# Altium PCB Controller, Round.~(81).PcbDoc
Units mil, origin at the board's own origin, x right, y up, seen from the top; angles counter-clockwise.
Board outline 1800 x 1800 mil, 4 copper layers (Top Layer, MidLayer1, MidLayer2, Bottom Layer); 43 components, 69 nets, 207 pads, 107 vias.
Unrouted connection lines stored in the file: 18.
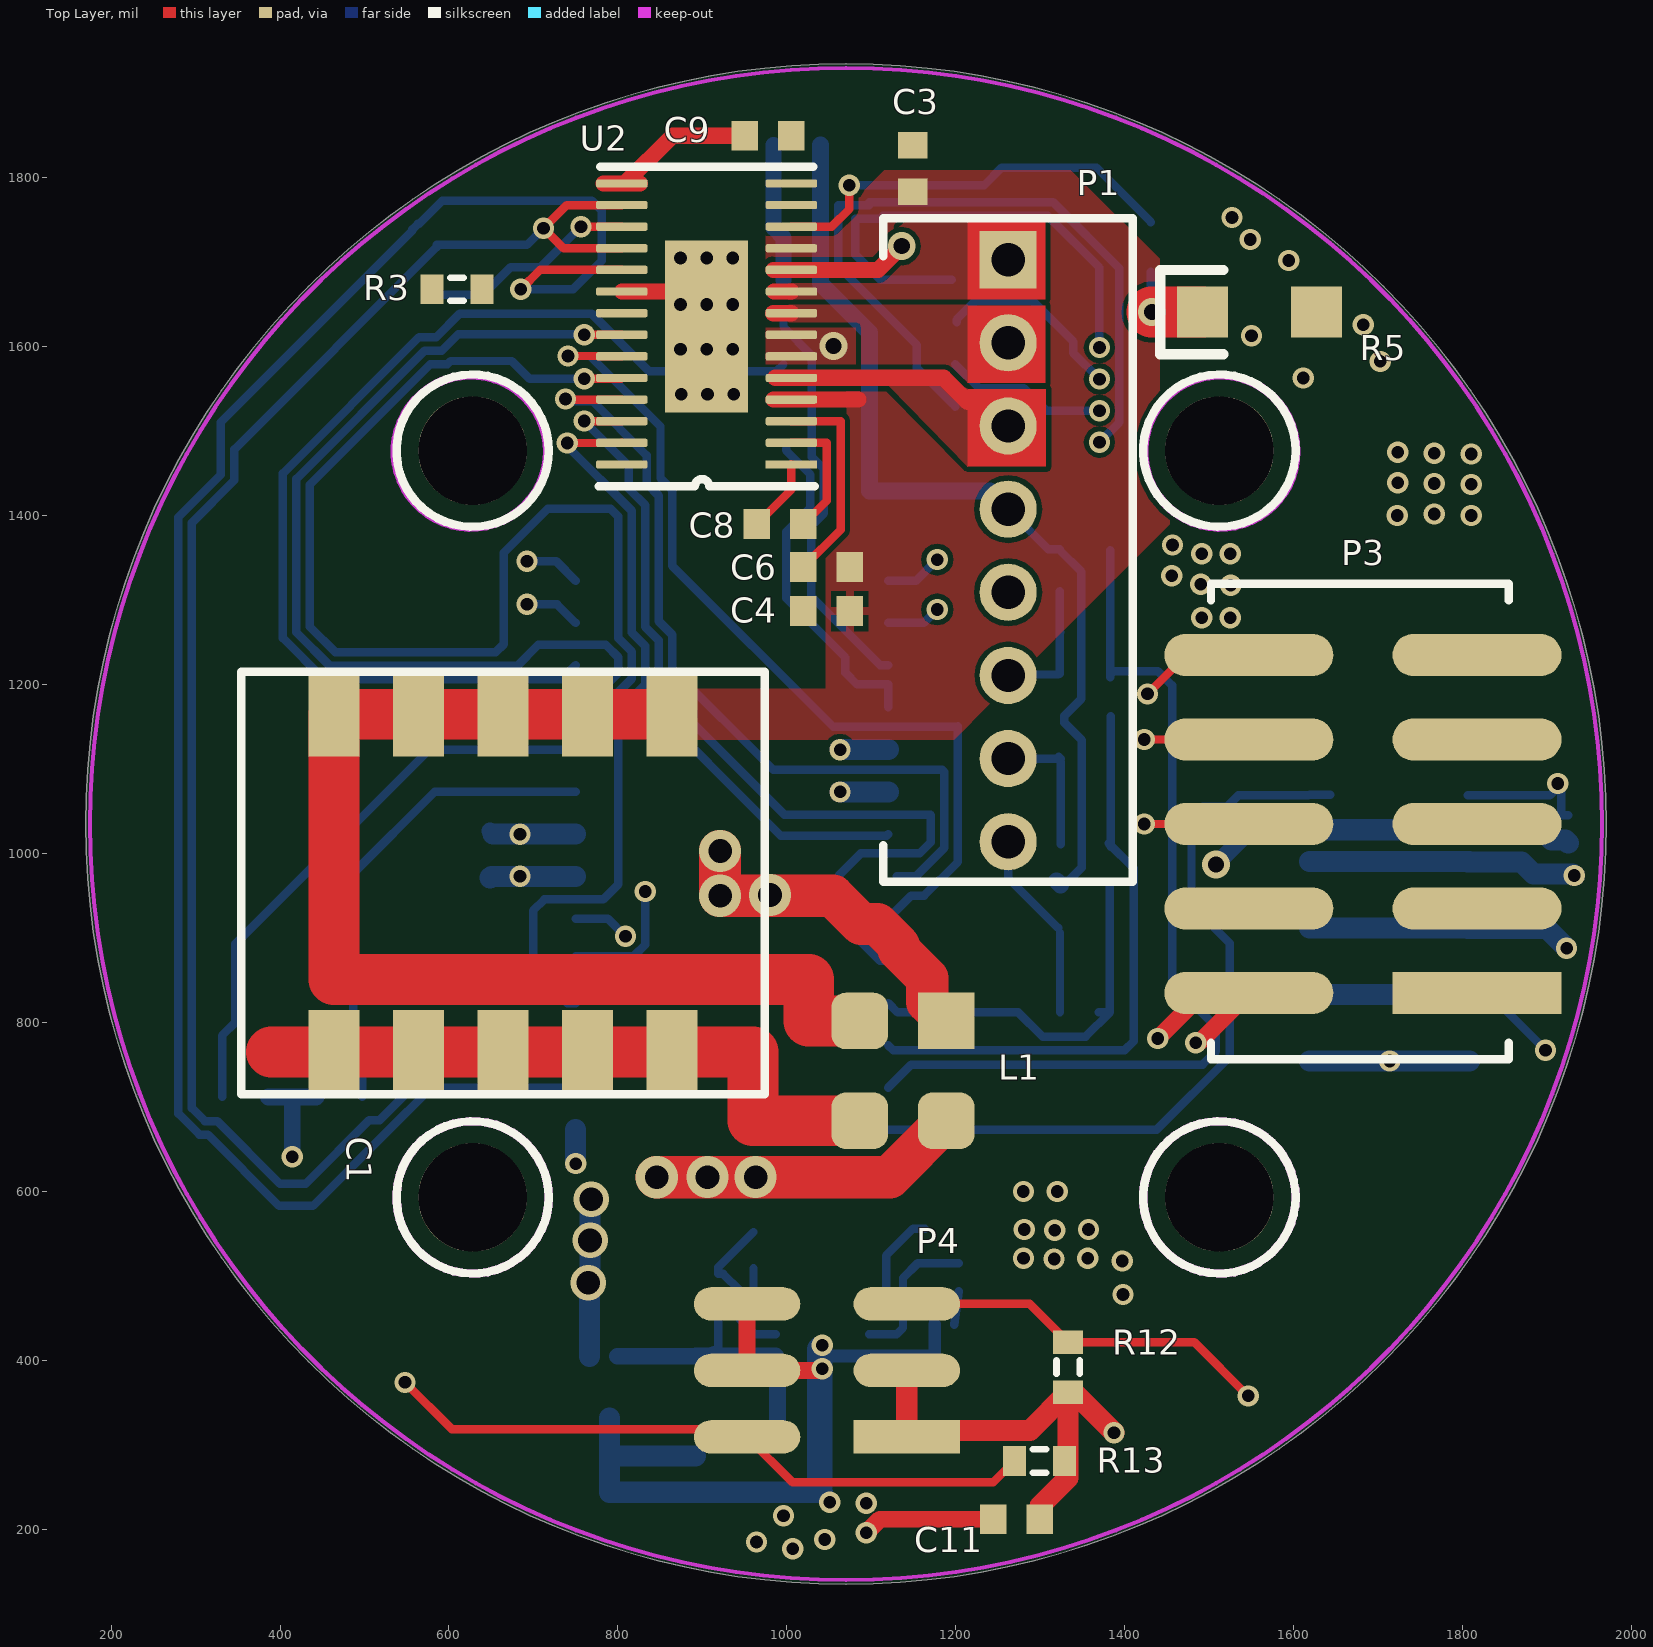
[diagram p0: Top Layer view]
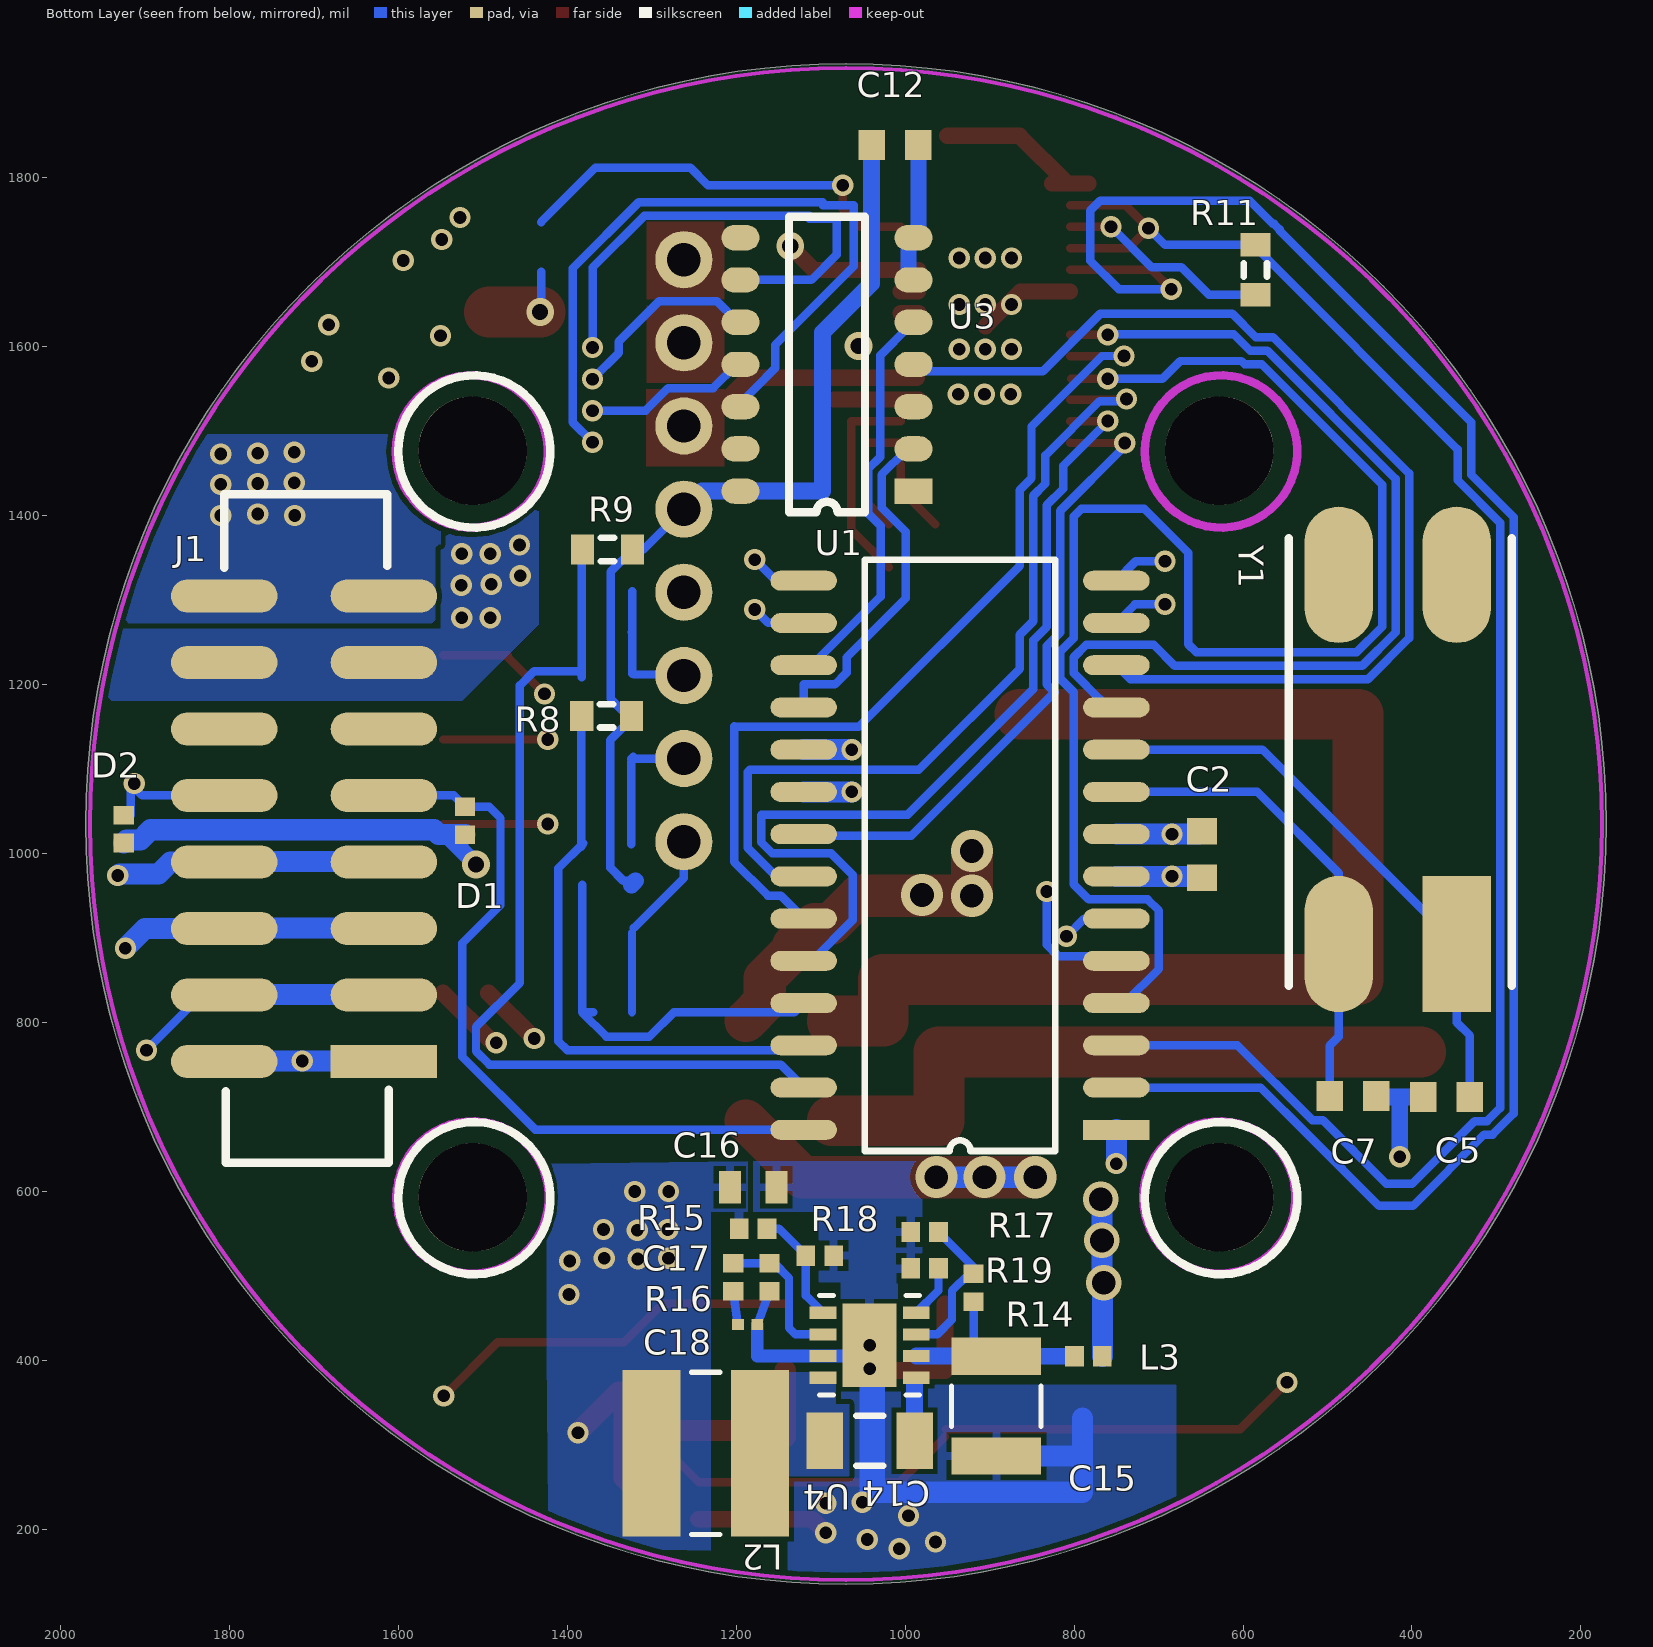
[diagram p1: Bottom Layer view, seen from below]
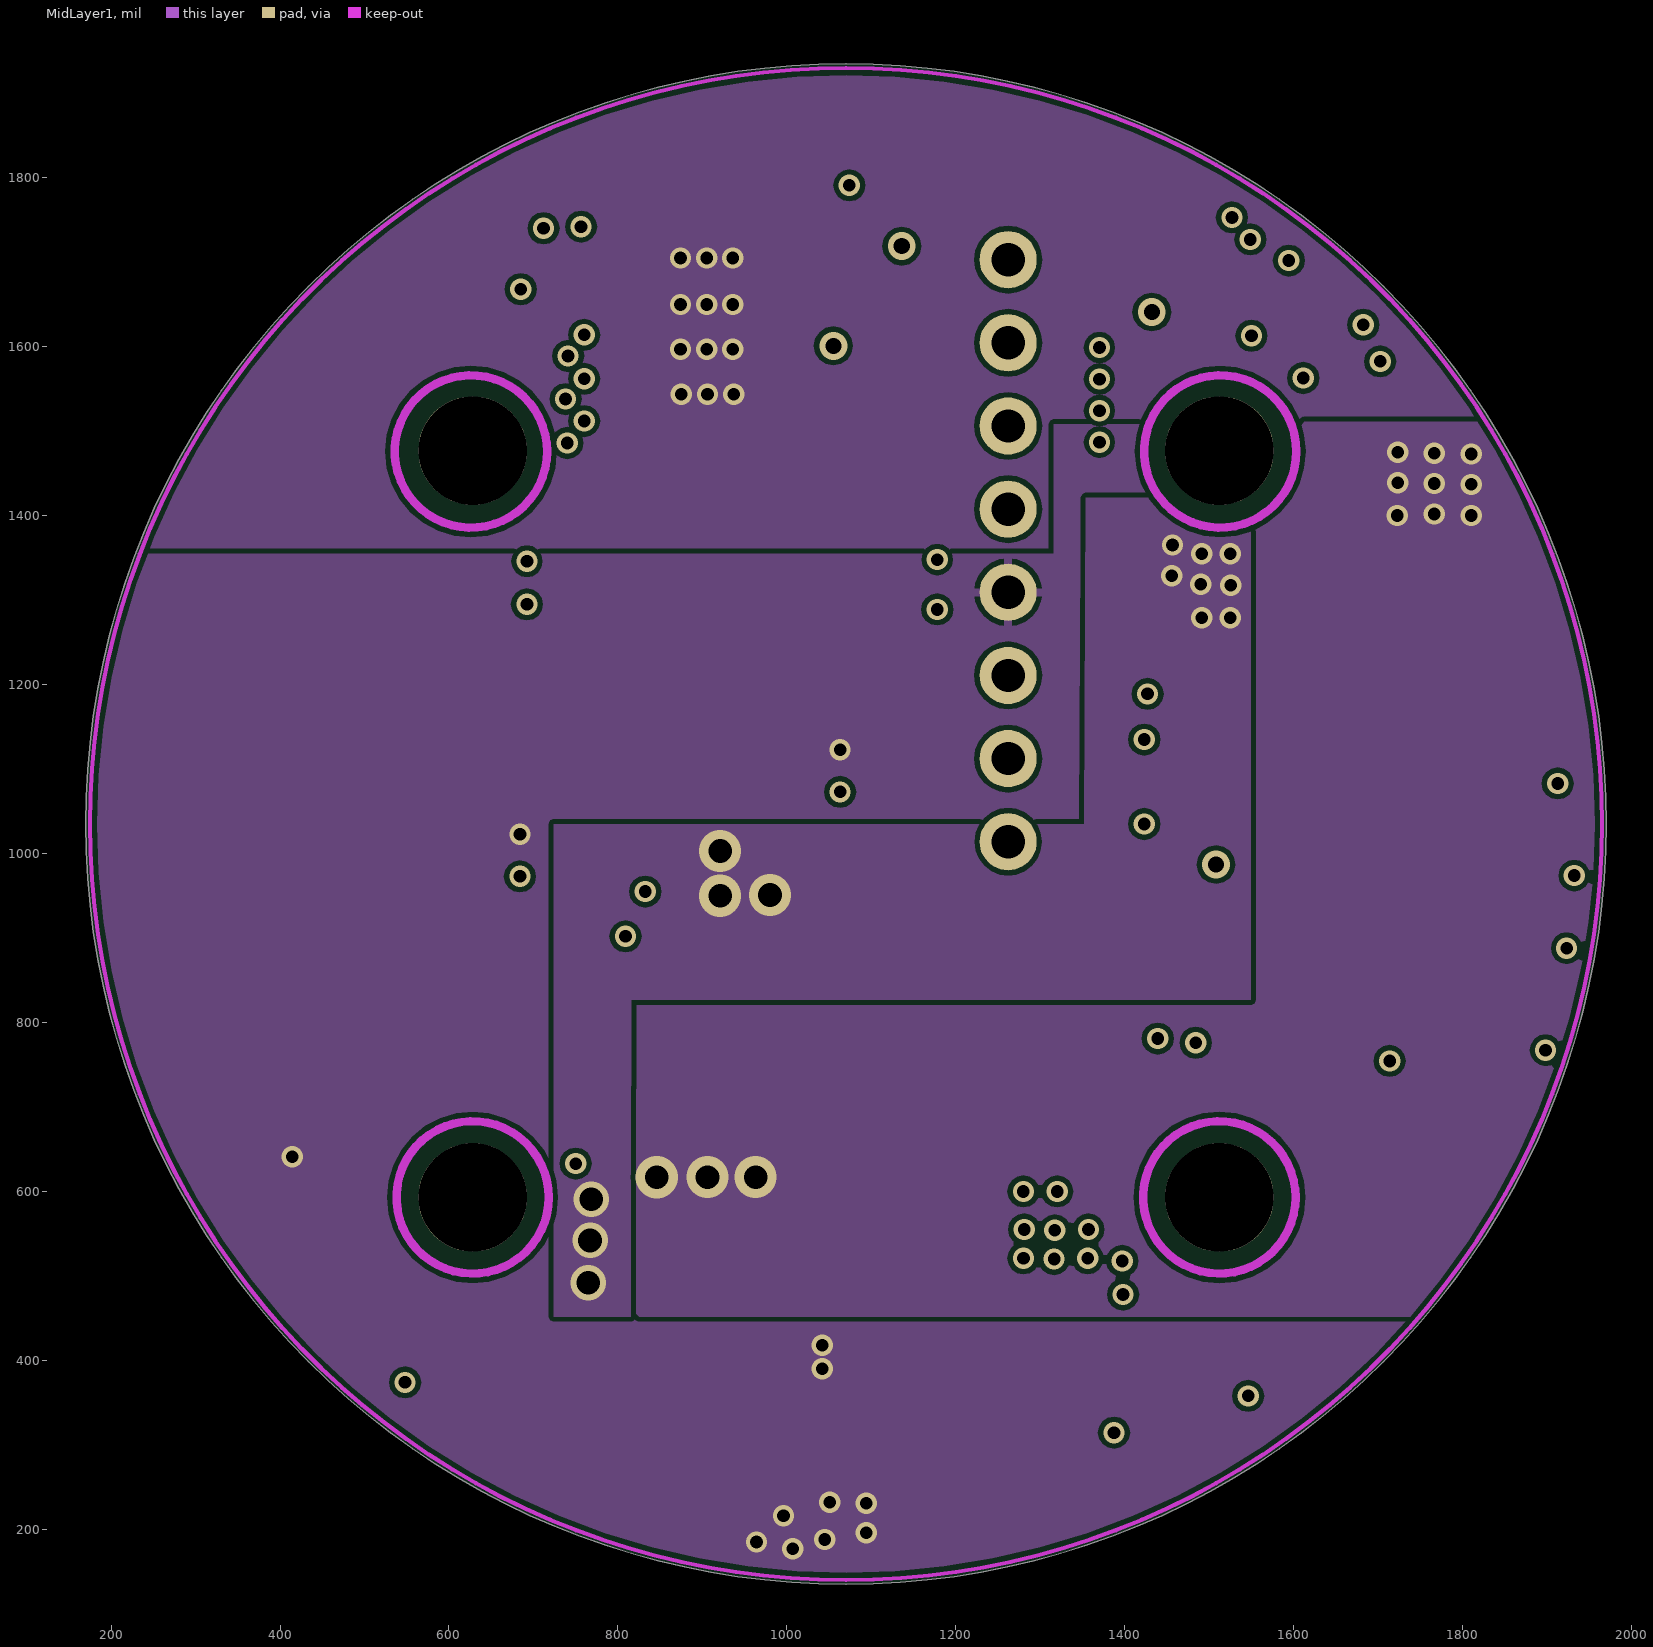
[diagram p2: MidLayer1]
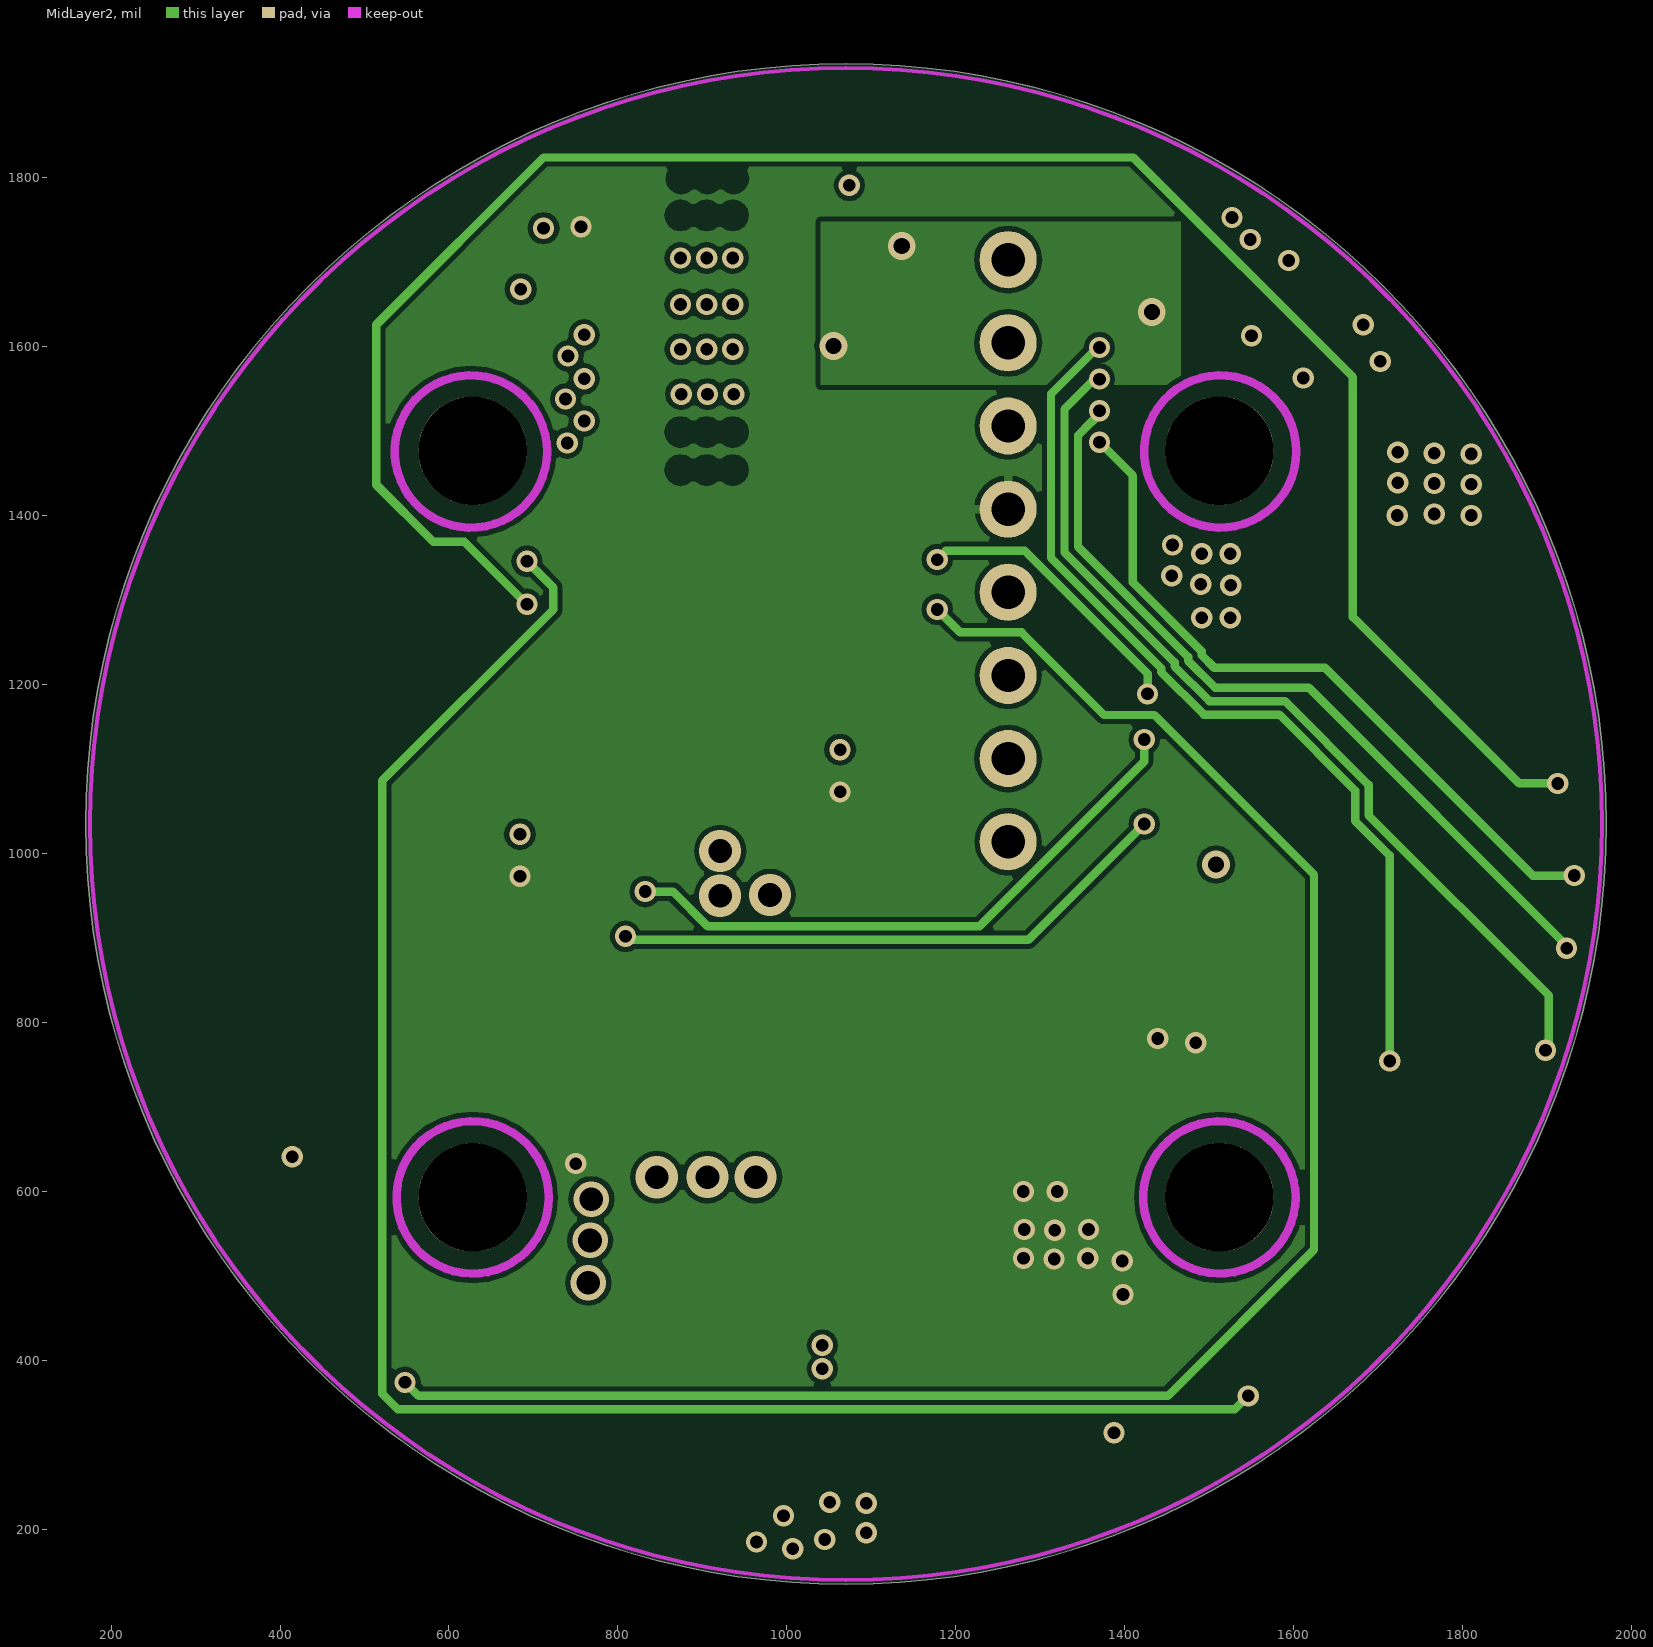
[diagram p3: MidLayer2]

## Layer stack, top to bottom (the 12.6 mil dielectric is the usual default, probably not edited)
Top Solder: solder mask 0.4, Solder Resist, Dk 3.5
Top Layer: signal copper 1.4
Dielectric1: core 12.6, FR-4, Dk 4.8
MidLayer1: signal copper 1.4
Dielectric2: prepreg 12.6, FR-4, Dk 4.8
MidLayer2: signal copper 1.4
Dielectric3: core 12.6, FR-4, Dk 4.8
Bottom Layer: signal copper 1.4
Bottom Solder: solder mask 0.4, Solder Resist, Dk 3.5

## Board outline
1070,135 cw(c1070,1035) 170,1035 cw(c1070,1035) 1070,1935 cw(c1070,1035) 1970,1035 cw(c1070,1035)

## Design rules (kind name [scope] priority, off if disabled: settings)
Clearance [All] p1: gap=6 ignorepadtopadclearanceinfootprint=FALSE except(0: Arc-Hole Track-Hole SMDPad-Hole THPad-Hole Via-Hole Fill-Hole Poly-Hole Region-Hole Text-Hole)
HoleSize [All] p1: absolutevalues=TRUE maxlimit=130 minlimit=15 maxpercent=80.000 minpercent=20.000
MinimumAnnularRing AdvancedCircuitsAnnularRing [All] p1: minimumring=5.1
MinimumSolderMaskSliver [All] p1: minsoldermaskwidth=5
PolygonConnect PolygonConnect_Via [IsVia] p1: connectstyle=Direct reliefconductorwidth=10 reliefentries=4 polygonreliefangle="90 Angle" airgapwidth=10
PolygonConnect PolygonConnect_7 [InComponent('U2') vs InNet('GND')] p2: connectstyle=Relief reliefconductorwidth=10 reliefentries=4 polygonreliefangle="90 Angle" airgapwidth=10
PolygonConnect PolygonConnect_6 [InComponent('L1') vs InNet('GND')] p3: connectstyle=NoConnect reliefconductorwidth=10 reliefentries=4 polygonreliefangle="90 Angle" airgapwidth=10
PolygonConnect PolygonConnect_5 [InComponent('L2') vs InNet('VCC')] p4: connectstyle=Direct reliefconductorwidth=10 reliefentries=4 polygonreliefangle="90 Angle" airgapwidth=10
PolygonConnect PolygonConnect_4 [(InComponent('R19') OR InComponent('R17') OR InComponent('U4')) vs InNet('SGND')] p5: connectstyle=Direct reliefconductorwidth=10 reliefentries=4 polygonreliefangle="90 Angle" airgapwidth=10
PolygonConnect PolygonConnect_3 [All vs InNet('NetC14_1')  or InNet('NetJ1_13')  or InNet('NetJ1_15')] p6: connectstyle=Direct reliefconductorwidth=10 reliefentries=4 polygonreliefangle="90 Angle" airgapwidth=10
PolygonConnect PolygonConnect_2 [InComponent('C4')] p7: connectstyle=Relief reliefconductorwidth=10 reliefentries=4 polygonreliefangle="90 Angle" airgapwidth=10
PolygonConnect PolygonConnect_1 [(InComponent('C1')) vs InNet('GND')] p8: connectstyle=NoConnect reliefconductorwidth=10 reliefentries=4 polygonreliefangle="90 Angle" airgapwidth=10
PolygonConnect [(InNet('NetP1_1') OR InNet('NetP1_2') OR InNet('NetP1_3') OR InNet('VM') OR InNet('VSENSE')) vs (InNet('NetP1_1') OR InNet('NetP1_2') OR InNet('NetP1_3') OR InNet('VM') OR InNet('VSENSE'))] p9: connectstyle=Direct reliefconductorwidth=10 reliefentries=4 polygonreliefangle="90 Angle" airgapwidth=10
RoutingVias RoutingVias_1 [(InNet('ADDR_IN') OR InNet('ADDR_OUT'))] p1: holewidth=15 width=25 viastyle="Through Hole" minholewidth=15 minwidth=25 maxholewidth=15 maxwidth=25
RoutingVias [All] p2: holewidth=15 width=25 viastyle="Through Hole" minholewidth=15 minwidth=25 maxholewidth=28 maxwidth=50
SilkToSolderMaskClearance SilkscreenOverComponentPads [IsPad] p1: minsilkscreentomaskgap=10 clearancetoexposedcopper=TRUE
SolderMaskExpansion [All] p1: expansion=4
Width Width_2 [All] p1: maxlimit=100 minlimit=6 preferedwidth=10 checkconnectedcopper=TRUE
Width Width_3 [InNet('VM')] p2: maxlimit=100 minlimit=20 preferedwidth=40
27 further rules are at their usual default settings.

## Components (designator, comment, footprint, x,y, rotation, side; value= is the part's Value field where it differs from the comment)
C1 "Cap" CAPSTICK-CS4-5-SMD 464,1165 r0 top value=10uf
C2 "Cap Semi" 1608[0603] 648.62,999 r90 bottom value=15pf
C3 "Cap Semi" 1608[0603] 1149,1811 r270 top value=.1uf
C4 "Cap Semi" 1608[0603] 1047,1287 r0 top value=.1uf
C5 "Cap Semi" 1608[0603] 359,712 r180 bottom value=15pf
C6 "Cap Semi" 1608[0603] 1047,1339 r0 top value=.1uf
C7 "Cap Semi" 1608[0603] 470,713 r0 bottom value=15pf
C8 "Cap Semi" 1608[0603] 992,1390 r180 top value=.01uf
C9 "Cap Semi" 1608[0603] 977.61,1849.7 r180 top value=.47uF
C11 "Cap Semi" 1608[0603] 1272,212 r0 top value=15pf
C12 "Cap Semi" 1608[0603] 1012,1839 r180 bottom value=15pf
C14 "C1005X7R1E103K" C1206 1042,305 r180 bottom value=10nF
C15 "C3225X7R2A225K230AB" 1210 892,346 r270 bottom value=2.2uF
C16 "C1608X5R0J106M" 0603 1180,605 r180 bottom value=10uF
C17 "C0402C330J5GAC" 0402 1160.5,498.5 r270 bottom value=33pF
C18 "GRM033R61A472KA01D" 0201 1186.5,442.5 r180 bottom value=4.7nF
D1 "Tranzorb" 0402 1521,1039 r90 bottom
D2 "Tranzorb" 0402 1925,1029 r90 bottom
J1 "M80-8281642" M80-828XXXXDIL 1806,1305 r180 bottom
L1 "DLW5BTN501SQ2" DLW5A_5B 1086.3,801.85 r0 top locked
L2 "LPS5030-823MLB" LPS5030 1236,290 r180 bottom value=82uH
L3 "INDUCTOR" 0402 783,405 r0 bottom
P1 "MKS 1658-6-0-808" MKS_1658_A_KF 1261.92,1703 r270 top locked
P3 "54202-G0805LF" N2510_SMD 1817,835 r180 top
P4 "M80-8280642" M8082806DIL 953,467 r0 top
R3 "Res3" J1-0603 609.47,1668 r0 top locked value=1K
R5 "Res3" 1206 1627,1641 r180 top value=.033
R8 "Res3" J1-0603 1353.34,1163 r180 bottom value=1K
R9 "Res3" J1-0603 1352.34,1360 r180 bottom value=1K
R11 "Res3" J1-0603 585.47,1691 r90 bottom value=1K
R12 "Res3" J1-0603 1333,392 r90 top value=1K
R13 "Res3" J1-0603 1299,281 r180 top value=1K
R14 "CRCW0402665KFKED" 0402 919,486 r90 bottom value=665k
R15 "CRCW040253K6FKED" 0402 1180,556 r180 bottom value=53.6k
R16 "CRCW040246K4FKED" 0402 1203.5,498.5 r90 bottom value=46.4k
R17 "CRCW040242K2FKED" 0402 977,552 r0 bottom value=42.2k
R18 "CRCW040210K0FKED" 0402 1101,524 r180 bottom value=10k
R19 "CRCW040280K6FKED" 0402 977,509 r0 bottom value=80.6k
U1 "PIC_SERVO_SC" SOP28 750,673 r0 bottom locked
U2 "DRV8313" HTSSOP28 1005.39,1460.61 r180 top
U3 "LTC2864xSOP" SOP14 990,1429 r0 bottom
U4 "TPS54061DRBR" S-PVSON-N8 1042,418 r0 bottom value=Value
Y1 "MA-506 10.0000M-C0" MA506 347,893 r0 bottom

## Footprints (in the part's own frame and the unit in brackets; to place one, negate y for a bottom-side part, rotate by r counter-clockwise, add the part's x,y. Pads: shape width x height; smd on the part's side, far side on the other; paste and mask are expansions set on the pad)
0201 [mil]
  rect 14x13 smd: 1(-11.5,0) 2(11.5,0)
0402 [mil]
  rect 22x24 smd: 1(-16.5,0) 2(16.5,0)
0603 [mil]
  rect 26x38 smd: 1(-27.5,0) 2(27.5,0)
1206 [mil]
  rect 60x60 smd: 1(0,0) 2(135,0)
  silkscreen extent 110,-50 185,50
1210 [mil]
  rect 44x106 smd: 1(-59,0) 2(59,0)
  silkscreen extent -24,-53 24,53
1608[0603] [mm] "Chip Capacitor, Body 1.6x0.8mm, IPC High Density"
  rect 0.8x0.9 smd: 1(-0.7,0) 2(0.7,0)
  body extent -0.87,-0.48 0.87,0.48, height 1.3
C1206 [mm] "Chip Capacitor, Body 3.2x1.6mm, IPC High Density"
  rect 1.1x1.7 smd: 1(-1.35,0) 2(1.35,0)
  silkscreen extent -0.4,-0.75 0.4,0.75, body extent -1.7,-0.9 1.7,0.9, height 1.3
CAPSTICK-CS4-5-SMD [mil]
  rect 60x100 smd: 1(0,0) 1(100,0) 1(200,0) 1(300,0) 1(400,0) 2(0,-400) 2(100,-400) 2(200,-400) 2(300,-400) 2(400,-400)
  silkscreen extent -110,-450 510,50
DLW5A_5B [mm]
  rect 1.7x1.7 smd: 1(2.6,0)
  rrect50% 1.7x1.7 smd: 2(0,0) 3(0,-3) 4(2.6,-3)
HTSSOP28 [mm] "HTTSSOP 28 Pin Package, TI"
  rect 1.55x0.25 smd: 1(0,0)
  rrect50% 1.55x0.25 smd: 2(0,-0.65) 3(0,-1.3) 4(0,-1.95) 5(0,-2.6) 6(0,-3.25) 7(0,-3.9) 8(0,-4.55) 9(0,-5.2) 10(0,-5.85) 11(0,-6.5) 12(0,-7.15) 13(0,-7.8) 14(0,-8.45) 15(5.1,-8.45) 16(5.1,-7.8) 17(5.1,-7.15) 18(5.1,-6.5) 19(5.1,-5.85) 20(5.1,-5.2) 21(5.1,-4.55) 22(5.1,-3.9) 23(5.1,-3.25) 24(5.1,-2.6) 25(5.1,-1.95) 26(5.1,-1.3) 27(5.1,-0.65) 28(5.1,0)
  rect 2.5x5.18 smd: Pad(2.55,-4.15)
  silkscreen extent -0.7,-8.95 5.8,0.65
J1-0603 [mm] "Chip Resistor, Body 1.6x0.8mm, IPC High Density"
  rect 0.7x0.9 smd: 1(-0.75,0) 2(0.75,0)
  silkscreen extent -0.2,-0.35 0.2,0.35, body extent -0.85,-0.48 0.85,0.48, height 0.9
LPS5030 [mil]
  rect 68.5x197 smd: 1(-64.25,0) 2(64.25,0)
  silkscreen extent -17,-96 17,96
M80-828XXXXDIL [mm]
  rect 3.2x1 smd: 1(4.8,-14)
  oval 3.2x1 smd: 2(0,-14) 3(4.8,-12) 4(0,-12) 5(4.8,-10) 6(0,-10) 7(4.8,-8) 8(0,-8) 9(4.8,-6) 10(0,-6) 11(4.8,-4) 12(0,-4) 13(4.8,-2) 14(0,-2) 15(4.8,0) 16(0,0)
  silkscreen extent 0,-17.05 4.95,3.05, body extent -1.38,-16.95 6.18,2.95, height 8.96
M8082806DIL [mm] "Harwin 2x3"
  rect 3.2x1 smd: 1(4.8,-4)
  oval 3.2x1 smd: 2(0,-4) 3(4.8,-2) 4(0,-2) 5(4.8,0) 6(0,0)
  body extent -1.38,-6.95 6.18,2.95, height 8.96
MA506 [mm]
  rect 2.05x4.1 smd: 1(0,0)
  oval 2.05x4.1 smd: 2(0,-11.1) 3(3.55,-11.1) 4(3.55,0)
  round 0.9 on Bottom Overlay: ""(-0.2,3.15)
  silkscreen extent -1.65,-12.2 5.05,1.26
MKS_1658_A_KF [mm] "Stocko MKS-1658 Shrouded Header Connector"
  rect 1.72x1.72 / inner round 1.72 / far side round 1.72 hole 1: 1(0,0)
  round 1.72 hole 1: 2(2.5,0) 3(5,0) 4(7.5,0) 5(10,0) 6(12.5,0) 7(15,0) 8(17.5,0)
  silkscreen extent -1.25,-3.75 18.7,3.75
N2510_SMD [mm]
  rect 5.08x1.27 smd: 1(0,0)
  oval 5.08x1.27 smd: 2(6.86,0) 3(0,-2.54) 4(6.86,-2.54) 5(0,-5.08) 6(6.86,-5.08) 7(0,-7.62) 8(6.86,-7.62) 9(0,-10.16) 10(6.86,-10.16)
  silkscreen extent -0.95,-12.3 8,2, body extent 0.03,-11.5 7.4,1.2, height 11.94
S-PVSON-N8 [mm]
  rect 0.805x0.37 smd: 1(-1.402,0.975) 2(-1.402,0.325) 3(-1.402,-0.325) 4(-1.402,-0.975) 5(1.402,-0.975) 6(1.402,-0.325) 7(1.402,0.325) 8(1.402,0.975)
  rect 1.626x2.5 smd paste-1.237 mask+0.152: 9(0,0)
  silkscreen extent -1.5,-1.5 1.5,1.5
SOP14 [mil]
  rect 45x30 smd: 1(0,0)
  oval 45x30 smd: 2(0,-50) 3(0,-100) 4(0,-150) 5(0,-200) 6(0,-250) 7(0,-300) 8(205,-300) 9(205,-250) 10(205,-200) 11(205,-150) 12(205,-100) 13(205,-50) 14(205,0)
  silkscreen extent 58,-325 148,25
SOP28 [mm]
  rect 2x0.6 smd: 1(0,0)
  oval 2x0.6 smd: 2(0,-1.27) 3(0,-2.54) 4(0,-3.81) 5(0,-5.08) 6(0,-6.35) 7(0,-7.62) 8(0,-8.89) 9(0,-10.16) 10(0,-11.43) 11(0,-12.7) 12(0,-13.97) 13(0,-15.24) 14(0,-16.51) 15(9.4,-16.51) 16(9.4,-15.24) 17(9.4,-13.97) 18(9.4,-12.7) 19(9.4,-11.43) 20(9.4,-10.16) 21(9.4,-8.89) 22(9.4,-7.62) 23(9.4,-6.35) 24(9.4,-5.08) 25(9.4,-3.81) 26(9.4,-2.54) 27(9.4,-1.27) 28(9.4,0)
  silkscreen extent 1.83,-17.14 7.56,0.64

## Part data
C1: "Capacitor", Distributor PartNo=338-3480-ND, Manufacturer="ITW Paktron", PartNo=106K050CS4G, Voltage=50V
C2: "Capacitor", Distributor PartNo=399-9005-1-ND, PartNo=C0603C150M8GACTU
C3 C4: "Capacitor", Distributor PartNo=311-1344-1-ND, Manufacturer=Yageo, PartNo=CC0603KRX7R9BB104
C5 C7 C11 C12: "Capacitor (Semiconductor SIM Model)", Distributor PartNo=399-9005-1-ND, Manufacturer=Kemet, PartNo=C0603C150M8GACTU
C6: "Capacitor (Semiconductor SIM Model)", Distributor PartNo=311-1344-1-ND, Manufacturer=Yageo, PartNo=CC0603KRX7R9BB104
C8: "Capacitor (Semiconductor SIM Model)", Distributor PartNo=399-1091-1-ND, Manufacturer=Kemet, PartNo=C0603C103K5RACTU
C9: "Capacitor (Semiconductor SIM Model)", Distributor PartNo=445-5952-1-ND, Manufacturer="TDK Corporation", PartNo=C1608X7R1H474K080AC
C14: Distributor PartNo=445-1260-1-ND, Manufacturer="TDK Corporation"
C15: "C3225X7R2A225K23", Distributor PartNo=445-4497-1-ND, Manufacturer="TDK Corporation"
C16: Distributor PartNo=445-4112-1-ND, Manufacturer="TDK Corporation"
C17: Distributor PartNo=399-1017-1-ND, Manufacturer=Kemet
C18: "GRM033R61A472KA0", Distributor PartNo=490-3164-1-ND, Manufacturer=MuRata
D1 D2: "Transient Voltage Suppression (TVS) Diode", Distributor PartNo=641-1294-1-ND, Manufacturer=Comchip, PartNo=CPDQR5V0
J1: Distributor PartNo=952-1166-5-ND, Manufacturer=Harwin
L1: library part "COMMON MODE CHOKE", Distributor PartNo=81-DLW5BTN501SQ2L, Manufacturer=Murata
L2: Distributor PartNo=994-LPS5030-823MLB, Manufacturer=Coilcraft
L3: "Inductor", Distributor PartNo=490-5442-1-ND, Manufacturer=Murata, PartNo=BLM15AX102SN1
P1: library part "Header 8", Distributor PartNo=353055, Manufacturer=Stocko
P3: library part "Header 5X2", "Header, 10-Pin, Dual row", Distributor PartNo=609-4723-ND, Manufacturer=FCI
P4: library part "Header 6", "Header, 6-Pin", Distributor PartNo=952-1161-5-ND, Manufacturer=Harwin
R3: "Resistor"
R5: "Resistor", Distributor PartNo=P.033AUCT-ND, Manufacturer=Panasonic, PartNo=ERJ-8BWFR033V
R8 R9 R11 R12 R13: "Resistor", Distributor PartNo=541-1.00KHCT-ND, Manufacturer="Vishay Dale", PartNo=CRCW06031K00FKEA
R14: Distributor PartNo=541-665KLCT-ND, Manufacturer=Vishay-Dale
R15: Distributor PartNo=541-53.6KLCT-ND, Manufacturer=Vishay-Dale
R16: Distributor PartNo=541-46.4KLCT-ND, Manufacturer=Vishay-Dale
R17: Distributor PartNo=541-42.2KLCT-ND, Manufacturer=Vishay-Dale
R18: Distributor PartNo=541-10.0KLCT-ND, Manufacturer=Vishay-Dale
R19: Distributor PartNo=541-80.6KLCT-ND, Manufacturer=Vishay-Dale
U1: Distributor PartNo=2134432, Manufacturer=jrkerr, PartNo=KAE-T0V10-SO
U2: Distributor PartNo=296-35540-5-ND, Manufacturer="Texas Instruments", PartNo=DRV8313PWPR
U3: Distributor PartNo=LTC2864IS-1#PBF-ND, Manufacturer="Linear Tech", PartNo=LTC2864IS-1#PBF
U4: "Imported", Distributor PartNo=296-30531-1-ND, Frequency=1100000.0, Manufacturer="Texas Instruments", Mktg_Package=TPS54061
Y1: library part MA-406/MA-505/MA-506, Distributor PartNo=SER2605CT-ND, Manufacturer=Epson

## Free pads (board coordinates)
  round 128.5 hole 128.5: ""(628,593) ""(628,1477) ""(1512,593) ""(1512,1477)

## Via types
v1: diameter 25.2, hole 15, Top Layer to Bottom Layer, 90 vias
v2: diameter 50, hole 28, Top Layer to Bottom Layer, 6 vias
v3: diameter 25.2, hole 15, Top Layer to Bottom Layer, tented top, 4 vias
v4: diameter 33, hole 19, Top Layer to Bottom Layer, 4 vias
v5: diameter 42, hole 28, Top Layer to Bottom Layer, 3 vias

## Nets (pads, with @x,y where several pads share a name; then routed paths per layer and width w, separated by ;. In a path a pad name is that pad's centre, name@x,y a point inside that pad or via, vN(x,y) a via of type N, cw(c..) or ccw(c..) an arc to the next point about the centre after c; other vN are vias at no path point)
\ENC_A: P3.5
\ENC_B: P3.7
\ENC_INDEX: P3.9
\FAULT: R11.2 U1.3 U2.16 U2.18 | length 2042.4
  Top Layer w10: U2.18 735.7,1716.52 v1(712,1740.22) 739.48,1767.7 U2.16
  Bottom Layer w10: v1(712,1740.22) 692.3,1720.53 R11.2 585.47,1717.84 346,1478.37 346,1441.99 295.65,1391.63 295.65,698.77 311.14,683.28 325.72,683.28 400,609 430.24,609 505.52,684.28 517.86,684.28 606.58,773 U1.3
ADDR_IN: D1.2 J1.9 U1.28 | length 950.8
  Bottom Layer w10: U1.28@1110.26,673 U1.28 1437.63,673 1524,759.37 1524,894 1479,939 1479,1042 1492.5,1055.5 D1.2 1534.28,1068.78 J1.9 1643.45,1069.45 J1.9@1619.02,1069.45
ADDR_OUT: D2.2 J1.10 U1.13 | length 2612.3
  MidLayer2 w10: v1(692.3,1295) 618.37,1368.93 581.65,1368.93 514,1436.59 514,1626 712,1824 1410,1824 1670,1564 1670,1280 1867,1083 v1(1912.44,1083)
  Bottom Layer w10: v1(692.3,1295) 728,1295 U1.13 ; J1.10 1903.3,1068.78 1912.44,1077.92 v1(1912.44,1083) 1916.61,1083 1916.61,1045.5 D2.2
CUR_SENSE: U1.2 U2.19 | length 2275.2
  Top Layer w10: v1(685,1668) 707.93,1690.93 U2.19
  Bottom Layer w10: 556.76,1737.45 330,1510.7 330,1448.62 279.65,1398.26 279.65,692.15 304.51,667.28 314.72,667.28 399,583 438.86,583 524.15,668.28 524.49,668.28 579.21,723 U1.2 ; 556.76,1738.86 563.2,1745.31 564.61,1745.31 592.3,1773 769,1773 781,1761 781,1702 747,1668 v1(685,1668)
ENC_A: P3.6 U1.6 | length 864
  Top Layer w10: v1(1423,1035) P3.6
  MidLayer2 w10: v1(809,902) 813,898 1286,898 v1(1423,1035)
  Bottom Layer w10: U1.6 788,923 v1(809,902)
ENC_B: P3.8 U1.5 | length 996.9
  Top Layer w10: v1(1423,1135) P3.8
  MidLayer2 w10: v1(832.37,955) 865.09,955 906.09,914 1228,914 1423,1109 v1(1423,1135)
  Bottom Layer w10: U1.5@750,878.4 818.78,878.4 832.6,892.22 832.6,954.77 v1(832.37,955) v1@825,955
ENC_INDEX: P3.10 U1.15 | length 621
  Top Layer w10: v1(1427,1189) P3.10@1473,1235 ; P3.10@1470.43,1235 P3.10 P3.10@1473.14,1235
  MidLayer2 w10: v1(1178,1348) 1188.21,1358.21 1281.79,1358.21 1427,1213 v1(1427,1189)
  Bottom Layer w10: U1.15 1153,1323 v1(1178,1348)
GND: C1.2 C3.1 C4.1 C9.1 L1.3 R3.1 R5.1 U2.14 U2.20 U2.28 U2.Pad | length 895.1
  Top Layer w19: U2.20 863.66,1665.34 U2.Pad
  Top Layer w60: 390,765 464,765 564,765 664,765 764,765 864,765 960,765 960,683.74 L1.3
  other v1: 875,1543.88 906,1543.88 937,1543.88 874,1597 905,1597 936,1597 874,1650 905,1650 936,1650 874,1705 905,1705 936,1705
HALL1: P1.8 U1.25 | length 220.5
  Bottom Layer w10: P1.8 1261.92,971.08 1321,912 ; 1323.34,812 1323.34,862 1323.34,906.02
HALL2: P1.7 R8.1 U1.26 | length 858
  Bottom Layer w10: U1.26 1125.79,767.28 1399.92,767.28 1410.36,777.72 1410.36,982.69 1381.06,1012 ; P1.7 1262.37,1112 1319.55,1112 ; 1321.89,1114.45 1321.89,1112 1324.34,1112 ; 1324.15,1011 1324.15,1108.55 ; 1383.39,1008.11 1383.39,1012 1383.39,1062 1383.39,1112 R8.1@1383.39,1162.47
HALL3: P1.6 R9.1 U1.27 | length 1253.6
  Bottom Layer w10: U1.27 1147.27,750.19 1492.19,750.19 1508,766 1508,795 1456,847 1456,1199 1439,1216 1384.53,1216 ; P1.6 1263.05,1212 1321.47,1212 ; 1322.94,1212.87 1322.94,1261.13 ; 1322.94,1310.43 1322.94,1261.13 ; 1323.81,1262 1322.94,1261.13 ; 1382.87,1208.64 1382.87,1212 ; R9.1@1382.87,1359 1382.87,1311.3 1382.87,1262 1382.87,1212 ; 1386.87,1216 1382.87,1212
LIMIT1: P4.2 R13.2 U1.16 | length 3015.2
  Top Layer w10: v1(548,374) 603.48,318.52 P4.2@952,318.52 ; P4.2 1006.92,255.6 1244.07,255.6 R13.2
  MidLayer2 w10: v1(548,374) 564,358 1451,358 1624,531 1624,975 1435,1164 1375.58,1164 1277.82,1261.75 1205.25,1261.75 v1(1178,1289)
  Bottom Layer w10: U1.16 1162,1273 v1(1178,1289)
LIMIT2: P4.5 R12.2 U1.14 | length 2638.1
  Top Layer w10: P4.5 1287.53,467 R12.2 1482.47,421.53 v1(1546,358)
  MidLayer2 w10: v1(692.3,1346) 723.69,1314.62 723.69,1288.91 520.93,1086.16 520.93,360.67 539.61,342 1530,342 v1(1546,358)
  Bottom Layer w10: v1(692.3,1346) 727,1346 U1.14
NetC5_2: C5.2 U1.10 Y1.1 | length 685.7
  Bottom Layer w10: C5.2 331.44,784.44 347,800 Y1.1 577,1123 U1.10
NetC6_1: C6.1 U2.3 | length 249.9
  Top Layer w10: U2.3 1064,1511.8 1064,1383.56 C6.1
NetC7_2: C7.2 U1.9 Y1.4 | length 572.3
  Bottom Layer w10: C7.2@497.56,712 497.56,772.44 486.76,783.24 Y1.4 486.76,976.76 583,1073 U1.9
NetC8_1: C8.1 U2.2 | length 154.3
  Top Layer w10: U2.2 1047,1486.2 1047,1417.44 C8.1 C8.1@1019.56,1395.14
NetC8_2: C8.2 U2.1 | length 87.6
  Top Layer w10: C8.2 1005.39,1430.95 U2.1
NetC14_1: C14.1 L2.2 U4.8
NetC14_2: C14.2 U4.1 | length 71
  Bottom Layer w20: C14.2 U4.1@988.85,376
NetC15_1: C15.1 L3.2 R14.1 U4.2 | length 271
  Bottom Layer w10: C15.1 919,414 R14.1
  Bottom Layer w20: L3.2 C15.1 ; C15.1@892.2,405.2 U4.2
NetC17_1: C17.1 R16.2 U4.6 | length 175.8
  Bottom Layer w10: U4.6 1129.8,430.8 1137.5,438.5 1137.5,497.56 1154.94,515 C17.1 R16.2
NetC18_1: C18.1 R16.1 | length 39.9
  Bottom Layer w10: C18.1 R16.1
NetJ1_13: J1.13 J1.14 L1.1 L3.1 | length 593.7
  Top Layer w50: v2(921,1003) v2(921,950) 1054.48,950 1087.98,916.5 1107.02,916.5 1132.5,891.02 1132.5,886.07 1166.3,852.27 1166.3,824.21 L1.1
  Bottom Layer w25: L3.1 766.5,490.5 v5(765,492) 767,483.25 v5(767,542) v5@767,579
  other v1: 1525,1279 1525.58,1317.71 1490,1318.73 1455.57,1329 1491,1355 1525,1355 1456.57,1365.27
  other v2: 980,951
  other v3: 1491,1279
  other v5: 768.52,590.97
NetJ1_15: J1.15 J1.16 L1.4 | length 470.4
  Top Layer w50: v2(846,616.85) 1121.77,616.85 L1.4
  Bottom Layer w25: v2@845,616.85 v2(846,616.85) v2@945,616.85
  other v1: 1722.5,1400.27 1810,1400.27 1766.25,1402 1810,1437 1766.5,1438 1723,1439 1810,1473 1766.5,1474 1723,1475
  other v2: 906,617 963,617
NetJ_1: 
NetJ_2: 
NetJ_3: 
NetJ_4: 
NetJ_5: 
NetJ_6: 
NetJ_7: 
NetJ_8: 
NetJ_9: 
NetJ_10: 
NetJ_11: 
NetJ_12: 
NetJ_13: 
NetJ_14: 
NetJ_15: 
NetJ_16: 
NetP1_1: P1.1 U2.9 | length 20.8
  Top Layer w19: U2.9@984.59,1665.34 U2.9
NetP1_2: P1.2 U2.8 | length 21.4
  Top Layer w19.5: U2.8@984,1639.75 U2.8
NetP1_3: P1.3 U2.5 | length 245.7
  Top Layer w19.5: U2.5@986,1562.98 1185.75,1562.98 1214,1534.73 ; 1223.57,1540 1226.57,1537 1227.82,1538.25
NetR2_1: R3.2 U2.13
NetR14_2: R14.2 R17.1 U4.3 | length 184.2
  Bottom Layer w10: R17.1 919,510.5 R14.2 924.56,502.5 944.5,482.56 944.5,448.3 962,430.8 U4.3
NetR15_2: R15.2 R18.1 U4.5 | length 135.3
  Bottom Layer w10: U4.5 1117.5,476.67 R18.1 1149.5,556 R15.2
NetR19_1: R19.1 U4.4 | length 63.5
  Bottom Layer w10: R19.1 960.5,482.67 U4.4
NetU1_4: U1.4 U2.24 | length 1819.7
  Top Layer w10: v1(760,1562) U2.24@803.63,1562
  Bottom Layer w10: U1.4 740.18,823 699.63,863.55 699.63,932.45 712.99,945.81 782.63,945.81 800.37,963.55 800.37,1190.92 816.37,1206.92 816.37,1239.08 800.37,1255.08 800.37,1399.14 791.51,1408 716.73,1408 665,1356.27 665,1247.6 664.8,1247.8 655.3,1238.3 465.49,1238.3 435.41,1268.38 435.41,1436.82 578,1579.42 598.29,1579.42 601.94,1583.07 674.35,1583.07 695.41,1562 v1(760,1562)
NetU1_11: U1.11 U2.22 | length 1148.1
  Top Layer w10: v1(760,1614) U2.22@804.45,1614 ; U2.22@780.65,1614.16 U2.22
  Bottom Layer w10: v1(760,1614) 759,1615 611.24,1615 591.66,1595.42 571.38,1595.42 419.41,1443.45 419.41,1261.75 458.86,1222.3 680.93,1222.3 705.63,1247 785.82,1247 800.37,1232.45 800.37,1213.55 769.24,1182.42 U1.11@769.24,1173
NetU1_12: U1.12 U3.4 | length 1271
  Bottom Layer w10: U1.12 733.3,1206.3 452.24,1206.3 403.41,1255.13 403.41,1450.08 564.75,1611.42 585.03,1611.42 612.62,1639 769,1639 837,1571 988,1571 U3.4@996,1579
NetU1_17: U1.17 U3.5 | length 475.4
  Bottom Layer w10: U3.5@996,1629 996,1623.27 1029.5,1589.77 1029.5,1469.45 1043.77,1455.18 1043.77,1402.82 1029,1388.05 1029,1304.26 1110.26,1223 U1.17
NetU1_18: U1.18 U3.2 | length 401.1
  Bottom Layer w10: U3.2@999.06,1479 999.06,1477.27 1027.77,1448.56 1027.77,1409.44 999.06,1380.73 999.06,1302.39 1069.35,1232.09 1069.35,1213.91 ; 1069.71,1213.55 1083.07,1200.19 1120.08,1200.19 U1.18
NetU1_21: U1.21 U2.27 | length 768.7
  Top Layer w10: v1@741,1486 804.4,1486 U2.27
  Bottom Layer w10: v1@741,1486 741,1481.14 816.37,1405.77 816.37,1261.7 832.37,1245.7 832.37,1200.3 823.04,1190.96 993,1021 1118.08,1021 U1.21
  other v1: 740,1486
NetU1_22: U1.22 U2.25 | length 982.2
  Top Layer w10: v1@741,1537.39 U2.25
  Bottom Layer w10: v1@741,1537.39 742.89,1535.5 750.12,1535.5 750.22,1535.6 769.78,1535.6 834,1471.38 834,1438.14 834.4,1437.74 834.4,1437.6 848.37,1423.63 848.37,1274.96 864.37,1258.96 864.37,1218.69 984.06,1099 1184,1099 1186.45,1096.55 1186.45,1006.92 1152.52,973 U1.22@1129.9,973
  other v1: 738,1538
NetU1_23: U1.23 U2.23 | length 1105.3
  Top Layer w10: v1(741,1589) 804.17,1589 U2.23 U2.23@777.43,1588.57
  Bottom Layer w10: v1@742.5,1590.5 v1(741,1589) 767,1589 850.4,1505.6 850.4,1444.22 864.37,1430.25 864.37,1340.63 1055,1150 1202,1150 1202.45,1150.45 1202.45,990.1 1162.53,950.19 1147.27,950.19 U1.23 U1.23@1129.9,923
NetU1_24: U1.24 U2.26 | length 1069.9
  Top Layer w10: v1(760,1512) 760.2,1511.8 U2.26
  Bottom Layer w10: v1(760,1512) 813,1459 813,1431.77 832.37,1412.4 832.37,1268.33 848.37,1252.33 848.37,1194.63 997,1046 1170,1046 1170.45,1045.55 1170.45,1013.55 ; U1.24 1110.26,873 1062,921.26 1062,974.74 1087.45,1000.19 1157.09,1000.19 1170,1013.1
RS422_RX_A: J1.7 J1.8 U3.12 | length 2106.9
  MidLayer2 w10: v1(1370,1487) 1409.58,1447.42 1409.58,1320.93 1491,1239.51 1491,1234.88 1505.88,1220 1637,1220 1883,974 v1(1932,974)
  Bottom Layer w10: U3.12@1195,1533.27 1176.73,1551.54 1176.73,1551.72 1154,1574.45 1154,1602 1061,1695 1061,1767.4 1097.6,1767.4 1097.6,1771 1315.37,1771 1393.6,1692.77 1393.6,1510.6 v1(1370,1487) v1@1366.37,1487 ; U3.12@1199.27,1529 U3.12@1199.27,1534.73 ; J1.7@1612.48,990.71 J1.7@1619.02,990.71 ; J1.8@1762,990.71 1762.68,990.04 J1.8
  Bottom Layer w25: J1.7@1619.02,990.71 1762,990.71 J1.8@1808,990.71 ; J1.8 1869.6,990.04 1883.64,976 1930,976 v1(1932,974)
RS422_RX_B: J1.5 J1.6 U3.11 | length 1467
  MidLayer2 w10: v1(1370,1524.33) 1370,1520.23 1360.37,1510.6 1360.22,1510.6 1344.65,1495.02 1344.65,1363.23 1475,1232.88 1475,1228.25 1506.84,1196.41 1617.82,1196.41 1923,891.23 v1(1923,888)
  Bottom Layer w10: U3.11@1199.27,1579 1227.26,1551.01 1280.51,1551.01 1307.18,1524.33 v1(1370,1524.33) ; J1.5@1612.48,911.97 J1.5@1619.02,911.97
  Bottom Layer w25: J1.5@1619.02,911.97 J1.6@1808,911.97 ; J1.6 1899.7,911.3 v1(1923,888)
RS422_TX_A: J1.3 J1.4 U3.10 | length 1641.6
  MidLayer2 w10: v1(1370,1561.67) 1364.15,1561.67 1328.65,1526.17 1328.65,1356.61 1459,1226.25 1459,1221.63 1500.21,1180.41 1589.59,1180.41 1688.72,1081.28 1688.72,1045.28 1902,832 1902,771.28 v1(1898,767.28)
  Bottom Layer w10: U3.10@1201,1629 1201,1632 1223,1654 1291,1654 1339,1606 1339,1592.67 v1(1370,1561.67) ; J1.4 1832.72,832.56 v1(1898,767.28)
  Bottom Layer w25: J1.3@1619.02,833.23 J1.4@1808,833.23
RS422_TX_B: J1.1 J1.2 U3.9 | length 1865.2
  MidLayer2 w10: v1(1370,1599) 1367.49,1599 1312.65,1544.16 1312.65,1349.98 1443,1219.63 1443,1215 1493.59,1164.41 1582.96,1164.41 1672.72,1074.65 1672.72,1038.65 1713.51,997.86 v1(1713.51,754.49)
  Bottom Layer w10: U3.9 1111,1679 1081,1709 1081,1751.4 1113.6,1751.4 1113.6,1755 1308.75,1755 1370,1693.75 v1(1370,1599) ; J1.2@1808,754.49 J1.2@1814.55,754.49
  Bottom Layer w25: J1.1@1619.02,754.49 v1(1713.51,754.49) J1.2@1808,754.49
SGND: C2.2 C5.1 C7.1 C11.1 C12.2 C15.2 C16.2 C17.2 C18.2 D1.1 D2.1 P1.5 P3.3 P4.4 P4.6 R17.2 R18.2 R19.2 U1.8 U1.19 U3.3 U3.6 U3.7 U4.7 U4.9 | length 2053.1
  Top Layer w20: P4.6 P4.4 1040.26,388.26 v1(1042,390) ; v1(1094,196) 1110,212 C11.1
  Bottom Layer w10: C17.2 C18.2
  Bottom Layer w15: U4.9@1042,405.2 U4.7 1175,405.2 C18.2
  Bottom Layer w19: C12.2 984.44,1740.56 996,1729 U3.6@996,1679
  Bottom Layer w20: C5.1 414.5,712 ; v1(414.5,641) 414.5,712 ; C7.1@442.44,712 414.5,712 ; C2.2 C2.2@652.18,1023 ; v4(1508,987) 1539,1018 1539,1022.5
  Bottom Layer w25: C2.2@652.18,1023 v1(684,1023) U1.8 ; 790.24,331.63 790.24,287 ; C15.2 790.24,287 ; 1042,244 790.24,244 790.24,287 ; v1(1063,1123) U1.19 ; D1.1 1539,1022.5 1552.18,1022.5 1557.9,1028.22 1893.11,1028.22 1905.34,1016 1921.5,1016 D2.1
  Bottom Layer w30: 1039,252 U4.9@1039,413.2
  other v1: 1007,177 964,185 1045,188 996,216 1093.82,231 1050.68,232 1042,418 1611.27,1562.93 1702.27,1582.59 1549.96,1612.96 1682.27,1626 1594.27,1702 1548.69,1727 1526.84,1753
V3P3: C9.2 R11.1 U2.15 | length 226
  Top Layer w19: U2.15@783,1793 826,1793 825.71,1793.29 808.29,1793.29 864.7,1849.7
  Top Layer w20: 864.7,1849.7 C9.2
VCC: C2.1 C11.2 C12.1 C16.1 L2.1 P1.4 P3.2 P4.1 P4.3 R8.2 R9.2 R12.1 R13.1 R15.1 U1.1 U1.7 U1.20 U2.17 U3.14 | length 2274
  Top Layer w10: v1(756.39,1742.11) U2.17
  Top Layer w20: v1(1439,781) P3.2@1493,835 ; v1(1484,776) 1487.92,776 P3.2
  Top Layer w25: P4.3 P4.1 1149.67,317.22 1287.74,317.22 R12.1 ; C11.2@1299.56,216.51 1299.56,227.56 1333,261 R12.1 ; v1(1387.25,314.52) 1339.3,362.47 R12.1
  Bottom Layer w10: 585.47,1661.47 640.47,1661.47 673,1694 708.28,1694 v1(756.39,1742.11) ; P1.4 R9.2@1309.65,1360 ; R9.2@1311.99,1360 R9.2 1322.81,1359.35 1348.59,1333.57 1348.59,1183.28 1328.31,1163 1328.31,1155.08 1349.12,1134.27 1349.12,983.28 1333.63,967.8 1319.02,967.8
  Bottom Layer w20: C12.1 1040,1838.56 1040,1675 1098,1617 1098,1429 1240.65,1429 P1.4 ; 1319.02,967.8 1323.81,963
  Bottom Layer w25: C2.1 650.18,973 v1(684,973) U1.7 ; v1(750,633) U1.1 ; v1(1063,1073) U1.20
  other v1: 1397,517.73 1316.34,520 1280.08,521 1317.27,554 1281,555 1280,600 1320,600
  other v3: 1398,478 1356.08,521 1357,555
VM: C1.1 C3.2 C4.2 C6.2 L1.2 U2.4 U2.11 | length 1486.3
  Top Layer w19: U2.4@984.02,1537.73 1005.39,1537.73 U2.4 1084.5,1537.39
  Top Layer w60: C1.1@864,1165 764,1165 664,1165 564,1165 464,1165 464,851 1026,851 1026,801.85 L1.2
VSENSE: R5.2 U2.6 U2.7 U2.10 U2.12 | length 770.2
  Top Layer w10: U2.12 1053.11,1742.11 1074,1763 v1(1074,1791)
  Top Layer w19: U2.10@984.02,1691 984.02,1690.93 U2.10 1107.93,1690.93 v4(1136,1719)
  Top Layer w60: v4(1432,1641) R5.2
  Bottom Layer w10: v1(1074,1791) 1233.37,1791 1254.37,1812 1366.53,1812 1431,1747.53 ; 1431,1688.47 1431,1641 v4@1432,1640
  other v4: 1055,1601
pads on no net: J1.11 J1.12 P3.1 P3.4 U2.21 U3.1 U3.8 U3.13 Y1. Y1.2 Y1.3
copper on no net: | length 452.7
  Bottom Layer w10: 1120.08,823 1131.08,812 1273.95,812 1302.66,783.28 ; 1305,783.28 1353.68,783.28 1382.39,812 ; 1368.98,812 1382.39,812 ; 1382.39,963 1382.39,912 1382.39,862 1382.39,812

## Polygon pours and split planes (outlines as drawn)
SGND on Bottom Layer "Top Layer-No Net" (solid, pour order 106): 1076,461 1076,492.64 1102,492.64 1102,576 1180,576 1180,636 980,636 980,494 1009,494 1009,461
NetC14_1 on Bottom Layer "Top Layer-No Net" (solid, pour order 102): 1082,386 1082,348 1066,348 1066,263 1154,263 1154,386
VCC on Bottom Layer "Top Layer-No Net" (solid, pour order 108): 1185,636 1185,576 1230,576 1230,175 1421.85,178 1424.33,407 1424.33,633
NetJ1_15 on Bottom Layer "Top Layer-No Net" (solid, pour order 116): 1550,1366 1550,1496.12 1549.54,1496.57 1890,1496.57 1907,1366
NetJ1_13 on Bottom Layer "Top Layer-No Net" (solid, remove dead copper, pour order 251): 2051.82,1266.45 1971.75,1181 1524,1181 1434,1271 1434,1421 1550,1421 1550,1266
NetJ1_15 on Bottom Layer "Top Layer-No Net" (solid, remove dead copper, pour order 253): 1550,1366 1550,1265 1990,1265 1991,1265 1991,1381 1991,1374.24 1550,1374.24
SGND on Bottom Layer "Top Layer-No Net" (solid, remove dead copper, pour order 249): 1139,371 1139,76 679,76 679,371
SGND on MidLayer1 "Top Layer-No Net" (solid, remove dead copper, pour order 185): 2106,53 2146,1355 -105,1355 -105,56
GND on MidLayer1 "Top Layer-No Net" (solid, remove dead copper, pour order 226): 112,1348 112,2011 1976,2011 1965,2011 1965,1331
SGND on MidLayer1 "Top Layer-No Net" (solid, pour order 187): 1316,1352 1316,1508 1430,1508 1443.75,1508 1443.75,1352
NetJ1_15 on MidLayer1 "Top Layer-No Net" (solid, remove dead copper, pour order 145): 1555.49,1373 1555.49,827 816,827 816,452 815,452 2029,452 2029,1371
NetJ1_15 on MidLayer1 "Top Layer-No Net" (solid, remove dead copper, pour order 189): 1593,1511 1919,1511 1923,1356 1538,1356
NetJ1_13 on MidLayer1 "Top Layer-No Net" (solid, pour order 139): 815,452 724,452 724,1035 1352,1035 1354,1421 1549,1421 1549,827 816,827
NetP1_2 on Top Layer "Top Layer-No Net" (solid, remove dead copper, pour order 236): 1002,1649.54 1214,1649.54 1214,1557 1002,1557.22
NetP1_3 on Top Layer "Top Layer-No Net" (solid, remove dead copper, pour order 255): 1121,1553 1214,1458 1214,1550 1185.75,1562.98 1121,1562.98
NetP1_1 on Top Layer "Top Layer-No Net" (solid, remove dead copper, pour order 228): 1214,1656 1002,1656 1002,1692 1075.74,1692 1141.41,1749 1214,1749
VM on Top Layer "Top Layer-No Net" (solid, remove dead copper, pour order 230): 975,1735 975,1692 1094,1692 1180,1692 1180,1810 1180,1809 1115,1809 1048,1742 1048,1735
VM on Top Layer "Top Layer-No Net" (solid, pour order 244): 1180,1809 1180,1755.49 1307.23,1755.49 1307.23,1757 1307.23,1545.87 1307,1545.87 1441.13,1545.87 1441.13,1547.87 1441.13,1703.87 1336,1809
VM on Top Layer "Top Layer-No Net" (solid, remove dead copper, pour order 257): 834,1195 1046,1195 1046,1375 1070.8,1375 1070.8,1548.56 1453,1548.56 1453,1390 1198,1135 833.27,1135
VSENSE on Top Layer "Top Layer-No Net" (solid, remove dead copper, pour order 232): 975,1622.72 1081.49,1622.72 1081.49,1579.03 975,1579.03
VCC on MidLayer2 "Top Layer-No Net" (solid, remove dead copper, pour order 265): 360,349 2045,349 2045,2075 2045,2081 -29,2081 16,2081 16,349
VSENSE on MidLayer2 "Top Layer-No Net" (solid, remove dead copper, pour order 238): 1040,1555 1466,1555 1466,1748 1040,1748

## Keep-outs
Keep-Out Layer:
  circle w5: c1070,1035 r895
  circle w10: c626,1476 r90.15
  circle w10: c1513,1476 r90.15
  circle w10: c1512,593 r90.15
  circle w10: c628,593 r90.15

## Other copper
Top Layer:
  rectangle net NetP1_1: 1214,1656 1306,1748
  rectangle net NetP1_2: 1214,1557 1306,1649
  rectangle net NetP1_3: 1214,1458 1307,1550

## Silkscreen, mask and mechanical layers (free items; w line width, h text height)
Top Overlay:
  circle w10: c1512,1477 r90.15
  circle w10: c1512,593 r90.15
  circle w10: c628,1477 r90.15
  circle w10: c628,593 r90.15
Bottom Overlay:
  circle w10: c1510,1476 r90.15
  circle w10: c1510,592 r90.15
  circle w10: c626,592 r90.15
Mechanical 1:
  circle w5: c1070,1035 r900
  circle w5: c628,1477 r64.25
  circle w5: c628,593 r64.25
  circle w5: c1512,593 r64.25
  circle w5: c1512,1477 r64.25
